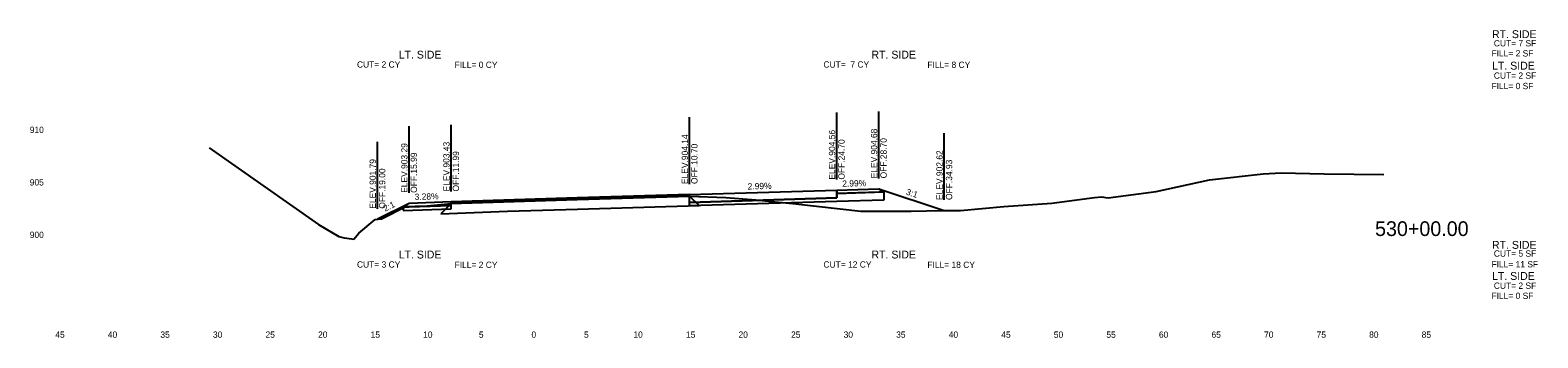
# Model space of a CAD drawing. Extents: x -4 to 359, y 0 to 1436.
# Drawn here: x -3.9 to 139.5, y 300.5 to 329.8 of the extents above; entities that cross this region are included whole.
import ezdxf

# ---------------------------------------------------------------- set-up
doc = ezdxf.new("R2010")
doc.units = 0
for name, color, linetype in [('XS-Existing subsurface-pavement', 7, 'Continuous'), ('XS-Existing surface-ground', 7, 'Continuous'), ('XS-Proposed Finish Grade', 7, 'Continuous'), ('XS-Proposed subsurface-aggregate layer 1', 7, 'Continuous'), ('XS-Proposed surface-ground', 7, 'Continuous'), ('XS-Proposed surface-pavement', 7, 'Continuous'), ('XS-Proposed surface-shoulder', 7, 'Continuous'), ('XS-Text-ditch slope', 7, 'Continuous'), ('XS-Text-earthwork labels', 7, 'Continuous'), ('XS-Text-elevation', 7, 'Continuous'), ('XS-Text-offset label', 7, 'Continuous'), ('XS-Text-pavement elevation', 7, 'Continuous'), ('XS-Text-pavement slope', 7, 'Continuous'), ('XS-Text-profile report', 7, 'Continuous'), ('XS-Text-shoulder elevation', 7, 'Continuous'), ('XS-Text-shoulder slope', 7, 'Continuous'), ('XS-Text-tie elevation', 7, 'Continuous'), ('XS-Text-tie offset', 7, 'Continuous')]:
    doc.layers.add(name, color=color, linetype=linetype)

msp = doc.modelspace()

# ---------------------------------------------------------------- linework, layer by layer
at = {"layer": 'XS-Existing subsurface-pavement'}
for p, q in [((36.14, 313.27), (35.17, 312.3)), ((41.49, 312.53), (48.16, 312.73)), ((48.16, 312.73), (59.74, 313.07)), ((58.83, 313.98), (59.74, 313.07)), ((35.17, 312.3), (41.49, 312.53))]:
    msp.add_line(p, q, dxfattribs=at)
at = {"layer": 'XS-Existing surface-ground'}
for p, q in [((13.11, 318.58), (23.53, 311.29)), ((108.3, 315.53), (113.4, 316.09)), ((113.4, 316.09), (115.11, 316.18)), ((115.11, 316.18), (119.2, 316.11)), ((119.2, 316.11), (124.87, 316.04)), ((98.66, 313.83), (103.21, 314.42)), ((103.21, 314.42), (108.3, 315.53)), ((29.51, 311.81), (31.89, 313.03)), ((31.89, 313.03), (32.79, 313)), ((32.79, 313), (33.08, 312.99)), ((33.08, 312.99), (33.55, 313.03)), ((33.55, 313.03), (36.14, 313.27)), ((36.14, 313.27), (41.46, 313.47)), ((41.46, 313.47), (48.13, 313.67)), ((48.13, 313.67), (58.83, 313.98)), ((58.83, 313.98), (62.28, 313.84)), ((62.28, 313.84), (65.12, 313.63)), ((65.12, 313.63), (66.63, 313.46)), ((66.63, 313.46), (68.64, 313.26)), ((68.64, 313.26), (75.11, 312.55)), ((84.6, 312.61), (88.72, 312.99)), ((88.72, 312.99), (93.3, 313.31)), ((93.3, 313.31), (97.34, 313.84)), ((97.34, 313.84), (98.03, 313.9)), ((98.03, 313.9), (98.66, 313.83)), ((23.53, 311.29), (25.47, 310.12)), ((27.36, 310.46), (28.91, 311.76)), ((28.91, 311.76), (29.51, 311.81)), ((75.11, 312.55), (79.9, 312.54)), ((79.9, 312.54), (81.37, 312.58)), ((81.37, 312.58), (82.89, 312.61)), ((82.89, 312.61), (84.6, 312.61)), ((25.47, 310.12), (25.98, 310.02)), ((25.98, 310.02), (26.69, 309.9)), ((26.69, 309.9), (26.9, 309.88)), ((26.9, 309.88), (27.36, 310.46))]:
    msp.add_line(p, q, dxfattribs=at)
at = {"layer": 'XS-Proposed Finish Grade'}
for points in [[(58.83, 314.13), (72.83, 314.55)], [(72.83, 314.55), (76.83, 314.67)], [(36.14, 313.42), (32.14, 313.29)], [(36.14, 313.42), (48.13, 313.81), (58.83, 314.13)]]:
    msp.add_lwpolyline(points, dxfattribs=at)
at = {"layer": 'XS-Proposed subsurface-aggregate layer 1'}
for points in [[(72.83, 314.24), (77.32, 314.37)], [(72.83, 313.8), (72.83, 314.24)], [(77.32, 314.37), (77.32, 313.6)], [(36.14, 313.1), (31.59, 312.95)], [(31.59, 312.95), (31.59, 312.62)], [(31.59, 312.62), (36.14, 312.77)], [(36.14, 312.77), (36.14, 313.1)], [(58.83, 313.38), (72.83, 313.8)], [(77.32, 313.6), (72.83, 313.47), (58.83, 313.05)], [(58.83, 313.05), (58.83, 313.38)]]:
    msp.add_lwpolyline(points, dxfattribs=at)
at = {"layer": 'XS-Proposed surface-ground'}
for points in [[(76.83, 314.67), (83.06, 312.61)], [(32.14, 313.29), (29.13, 311.78)]]:
    msp.add_lwpolyline(points, dxfattribs=at)
at = {"layer": 'XS-Proposed surface-pavement'}
for points in [[(58.83, 314.13), (72.83, 314.55)], [(72.83, 314.55), (72.83, 313.8)], [(58.83, 314.13), (48.13, 313.81), (36.14, 313.42)], [(36.14, 313.27), (48.13, 313.66), (58.83, 313.98)], [(36.14, 313.42), (36.14, 313.27)], [(58.83, 313.38), (58.83, 314.13)], [(58.83, 313.98), (58.83, 314.13)], [(72.83, 313.8), (58.83, 313.38)]]:
    msp.add_lwpolyline(points, dxfattribs=at)
at = {"layer": 'XS-Proposed surface-shoulder'}
for points in [[(72.83, 314.55), (76.83, 314.67), (77.32, 314.37)], [(72.83, 314.24), (72.83, 314.55)], [(77.32, 314.37), (76.83, 314.36), (72.83, 314.24)], [(36.14, 313.42), (32.14, 313.29), (31.59, 312.95)], [(31.59, 312.95), (32.14, 312.97), (36.14, 313.1)], [(36.14, 313.1), (36.14, 313.42)]]:
    msp.add_lwpolyline(points, dxfattribs=at)
at = {"layer": 'XS-Text-tie offset'}
for p, q in [((58.83, 315.13), (58.83, 321.48)), ((72.83, 315.55), (72.83, 321.93)), ((76.83, 315.67), (76.83, 322.02)), ((32.14, 314.29), (32.14, 320.64)), ((36.14, 314.42), (36.14, 320.77)), ((83.06, 313.61), (83.06, 319.96)), ((29.13, 312.78), (29.13, 319.13))]:
    msp.add_line(p, q, dxfattribs=at)

# ---------------------------------------------------------------- texts
at = {"layer": 'XS-Text-ditch slope'}
for s, rotation, p in [('3:1', 341.7371, (79.37, 314.14)), ('2:1', 26.5651, (29.87, 312.49))]:
    msp.add_text(s, height=0.6, rotation=rotation, dxfattribs=at).set_placement(p)
at = {"layer": 'XS-Text-earthwork labels'}
for s, height, p in [('RT. SIDE', 0.75, (135.17, 329.02)), (' CUT= 7 SF           ', 0.6, (135.12, 328.23)), ('LT. SIDE', 0.75, (31.15, 327.07)), ('RT. SIDE', 0.75, (76.13, 327.07)), ('FILL= 2 SF           ', 0.6, (135.12, 327.27)), (' CUT= 2 CY           ', 0.6, (26.96, 326.21)), ('FILL= 0 CY           ', 0.6, (36.47, 326.18)), (' CUT=  7 CY           ', 0.6, (71.34, 326.21)), ('FILL= 8 CY           ', 0.6, (81.45, 326.18)), ('LT. SIDE', 0.75, (135.17, 326.02)), (' CUT= 2 SF           ', 0.6, (135.12, 325.15)), ('FILL= 0 SF           ', 0.6, (135.12, 324.16)), ('LT. SIDE', 0.75, (31.15, 308.04)), ('RT. SIDE', 0.75, (76.13, 308.04)), ('RT. SIDE', 0.75, (135.17, 308.96)), (' CUT= 5 SF           ', 0.6, (135.12, 308.21)), (' CUT= 3 CY           ', 0.6, (26.96, 307.17)), ('FILL= 2 CY           ', 0.6, (36.47, 307.14)), (' CUT= 12 CY           ', 0.6, (71.34, 307.17)), ('FILL= 18 CY           ', 0.6, (81.45, 307.14)), ('FILL= 11 SF           ', 0.6, (135.12, 307.19)), ('LT. SIDE', 0.75, (135.17, 306)), (' CUT= 2 SF           ', 0.6, (135.12, 305.15)), ('FILL= 0 SF           ', 0.6, (135.12, 304.19))]:
    msp.add_text(s, height=height, dxfattribs=at).set_placement(p)
at = {"layer": 'XS-Text-elevation'}
for s, p in [('           910           ', (-6.4, 319.99)), ('           905           ', (-6.4, 314.99)), ('           900           ', (-6.4, 309.99))]:
    msp.add_text(s, height=0.6, dxfattribs=at).set_placement(p)
at = {"layer": 'XS-Text-offset label'}
for s, height, p in [('           530+00.00           ', 1.4, (118.32, 310.18)), ('           45           ', 0.6, (-3.97, 300.49)), ('           40           ', 0.6, (1.03, 300.49)), ('           35           ', 0.6, (6.03, 300.49)), ('           30           ', 0.6, (11.03, 300.49)), ('           25           ', 0.6, (16.03, 300.49)), ('           20           ', 0.6, (21.03, 300.49)), ('           15           ', 0.6, (26.03, 300.49)), ('           10           ', 0.6, (31.03, 300.49)), ('           5           ', 0.6, (36.33, 300.49)), ('           0           ', 0.6, (41.33, 300.49)), ('           0           ', 0.6, (41.33, 300.49)), ('           5           ', 0.6, (46.33, 300.49)), ('           10           ', 0.6, (51.03, 300.49)), ('           15           ', 0.6, (56.03, 300.49)), ('           20           ', 0.6, (61.03, 300.49)), ('           25           ', 0.6, (66.03, 300.49)), ('           30           ', 0.6, (71.03, 300.49)), ('           35           ', 0.6, (76.03, 300.49)), ('           40           ', 0.6, (81.03, 300.49)), ('           45           ', 0.6, (86.03, 300.49)), ('           50           ', 0.6, (91.03, 300.49)), ('           55           ', 0.6, (96.03, 300.49)), ('           60           ', 0.6, (101.03, 300.49)), ('           65           ', 0.6, (106.03, 300.49)), ('           70           ', 0.6, (111.03, 300.49)), ('           75           ', 0.6, (116.03, 300.49)), ('           80           ', 0.6, (121.03, 300.49)), ('           85           ', 0.6, (126.03, 300.49))]:
    msp.add_text(s, height=height, dxfattribs=at).set_placement(p)
at = {"layer": 'XS-Text-pavement elevation'}
for s, p in [('ELEV.904.56', (72.68, 315.55)), ('ELEV.903.29', (31.99, 314.29)), ('ELEV.903.43', (35.99, 314.42)), ('ELEV.904.14', (58.68, 315.13)), ('OFF.10.70', (59.58, 315.13)), ('OFF.24.70', (73.58, 315.55)), ('OFF.15.99', (32.89, 314.29)), ('OFF.11.99', (36.89, 314.42))]:
    msp.add_text(s, height=0.6, rotation=90, dxfattribs=at).set_placement(p)
at = {"layer": 'XS-Text-pavement slope'}
msp.add_text('2.99%', height=0.6, rotation=1.7131, dxfattribs=at).set_placement((64.36, 314.6))
at = {"layer": 'XS-Text-profile report'}
for s, p in [('Pvmt_Surf_Conc_T1_R', (72.81, 314.55)), ('Shldr_Surf_Asph_B111', (72.81, 314.24)), ('Shldr_Surf_Asph_T11', (76.81, 314.67)), ('Shldr_Surf_Asph_B11', (76.81, 314.35)), ('Shldr_Surf_Asph_B21', (77.31, 314.37)), ('Shldr_Surf_Asph_B2', (31.58, 312.95)), ('Shldr_Surf_Asph_T1', (32.13, 313.28)), ('Shldr_Surf_Asph_B1', (32.13, 312.97)), ('Pvmt_Surf_Asph_T2_L', (36.13, 313.42)), ('Pvmt_Surf_Asph_T_L', (36.13, 313.27)), ('Shldr_Surf_Asph_B12', (36.13, 313.1)), ('Agg_Layer_1_B', (36.13, 312.77)), ('Pvmt_Surf_Asph_T1', (48.12, 313.81)), ('Pvmt_Surf_Asph_T', (48.12, 313.66)), ('Pvmt_Surf_Asph_T1_R', (58.81, 314.13)), ('Pvmt_Surf_Asph_T_R', (58.81, 313.98)), ('Pvmt_Surf_Conc_B_R', (58.81, 313.38)), ('Agg_Layer_1_B2', (58.82, 313.05)), ('Pvmt_Surf_Conc_B1_R', (72.81, 313.8)), ('Agg_Layer_1_B11', (72.82, 313.46)), ('Agg_Layer_1_B12', (77.31, 313.6)), ('Rt_Agg_Layer_1_B13', (79.82, 313.67)), ('Fill_Slope_2_B', (29.11, 311.78)), ('Agg_Layer_1_B1', (31.58, 312.62)), ('Fill_Slope_2_B1', (83.04, 312.61))]:
    msp.add_text(s, height=0.00167, dxfattribs=at).set_placement(p)
at = {"layer": 'XS-Text-shoulder elevation'}
for s, p in [('ELEV.904.68', (76.68, 315.67)), ('OFF.28.70', (77.58, 315.67))]:
    msp.add_text(s, height=0.6, rotation=90, dxfattribs=at).set_placement(p)
at = {"layer": 'XS-Text-shoulder slope'}
for s, rotation, p in [('3.28%', 1.8802, (32.68, 313.6)), ('2.99%', 1.7131, (73.36, 314.86))]:
    msp.add_text(s, height=0.6, rotation=rotation, dxfattribs=at).set_placement(p)
at = {"layer": 'XS-Text-tie elevation'}
for s, p in [('ELEV.901.79', (28.98, 312.78)), ('ELEV.902.62', (82.91, 313.61)), ('OFF.34.93', (83.81, 313.61)), ('OFF.19.00', (29.88, 312.78))]:
    msp.add_text(s, height=0.6, rotation=90, dxfattribs=at).set_placement(p)

doc.saveas('drawing.dxf')
